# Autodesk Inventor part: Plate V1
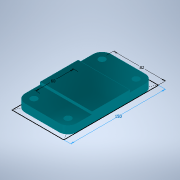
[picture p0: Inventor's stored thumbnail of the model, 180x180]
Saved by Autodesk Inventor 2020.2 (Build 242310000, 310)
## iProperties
Created: 2018-06
Part Number: Plate V1
Material: Aluminum 6061
Document SubType Name: Modeling
Designer: Power User
Density: 2.7 g/cm^3
Appearance: Steel - Polished(2)
Mass: 398.831 g
Surface Area: 289.267 cm^2
Volume: 147.715 cm^3
Author: Power User
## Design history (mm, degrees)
sketch "Sketch1"
  geometry: L1 (41, 68)-(-41, 68); L2 (-41, 68)-(-41, -68); L3 (-41, -68)-(41, -68); L4 (41, -68)-(41, 68); L5 (41, 68)-(-41, -68); L6 (-41, 68)-(41, -68); L7 (-41, -30)-(41, -30); L8 (41, -30)-(41, 30); L9 (41, 30)-(-41, 30); L10 (-41, 30)-(-41, -30); L11 (-41, -30)-(41, 30); L12 (41, -30)-(-41, 30); 1 further point
  constraints: 24 end point, 4 midpoint, 4 parallel, 2 horizontal, 2 perpendicular, 1 collinear
  dimensions: "d0" = 82 distance of L3.end L2.end; "d1" = 136 distance of L2.end L1.end; "d3" = 60 distance between parallel lines of L7 L9
extrude "Extrusion1" new body sketch "Sketch1" distance "d4" = 12; taper "d5" = 0 deg
extrude "Extrusion2" join sketch "Sketch1" distance "d6" = 16; taper "d7" = 0 deg
fillet "Fillet1" dims "d8" = 14
sketch "Sketch3"
  geometry: A1 r 14 centre (-27, -54) between (-41, -54) and (-27, -68) reference; A2 r 14 centre (-27, 54) between (-27, 68) and (-41, 54) reference; A3 r 14 centre (27, 54) between (41, 54) and (27, 68) reference; A4 r 14 centre (27, -54) between (27, -68) and (41, -54) reference; 5 further points
  constraints: 4 coincident
hole "Hole2" sketch "Sketch3" at (-27, -54), (-27, 54), (27, 54), (27, -54) diameter "d16" = 10; stored, may be unused: countersink angle "d20" = 90 deg, drill point angle "d22" = 118 deg; dims "d17" = 6, "d18" = 4, "d19" = 2, "d21" = 8
body "Solid1"
sketch "Sketch4"
  geometry: 1 further point
